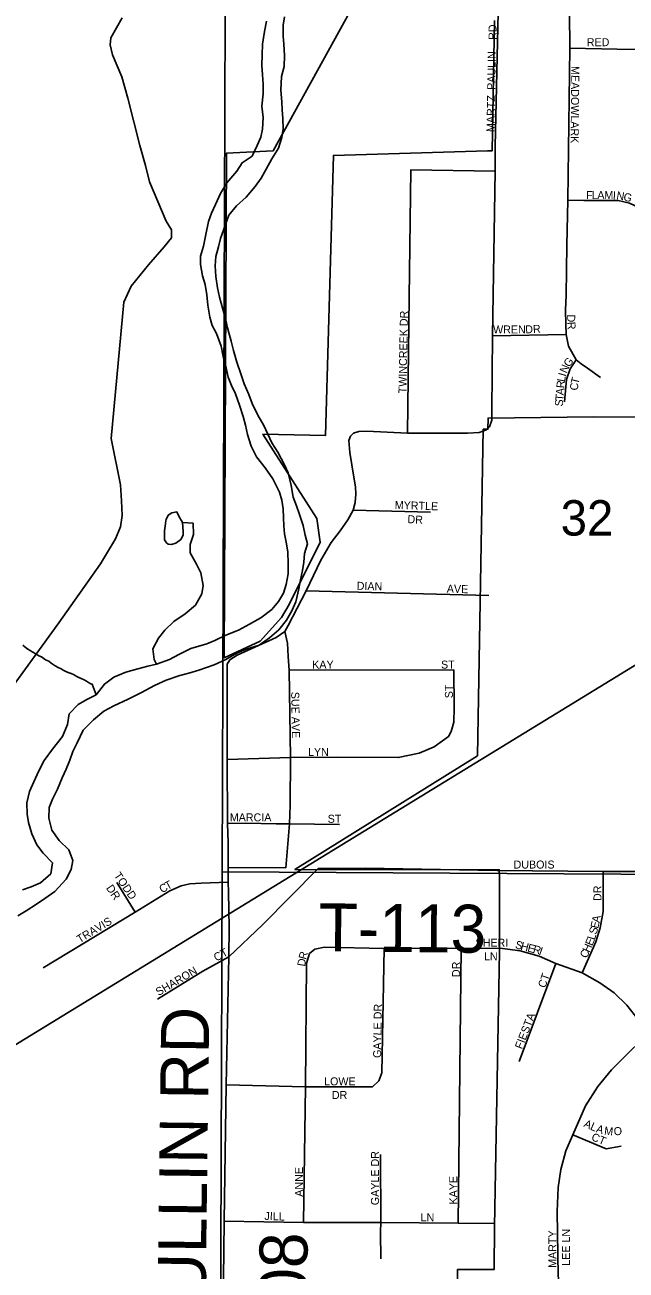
# Model space of a CAD drawing. Extents: x 0 to 1064, y 0 to 440.
# Drawn here: x 123.81 to 135.19, y 382.83 to 406.41 of the extents above; entities that cross this region are included whole.
import ezdxf

# ---------------------------------------------------------------- set-up
doc = ezdxf.new("R2010")
doc.units = 0
for name, color, linetype in [('GM_X_City_Street', 7, 'Continuous'), ('GM_X_City_Street_Text', 7, 'Continuous'), ('GM_X_Corporation', 7, 'Continuous'), ('GM_X_Major_River', 7, 'Continuous'), ('GM_X_Minor_River', 7, 'Continuous'), ('GM_X_Rail_Line', 7, 'Continuous'), ('GM_X_Section', 7, 'Continuous'), ('GM_X_Section_Text', 7, 'Continuous'), ('GM_X_Township_Road', 7, 'Continuous'), ('GM_X_Township_Road_Text', 7, 'Continuous'), ('GM_X_Township_Subdivision', 7, 'Continuous'), ('GM_X_Township_Subdivision_Text', 7, 'Continuous')]:
    doc.layers.add(name, color=color, linetype=linetype)

msp = doc.modelspace()

# ---------------------------------------------------------------- linework, layer by layer
at = {"layer": 'GM_X_City_Street'}
for points in [[(132.714, 404.106), (132.772, 406.652)], [(132.75, 390.394), (134.757, 390.374), (136.62, 390.376), (136.91, 390.371), (137.013, 390.348), (137.089, 390.3), (137.137, 390.226), (137.163, 389.662), (137.204, 389.562), (137.277, 389.485), (137.431, 389.468), (143.546, 390.366), (143.775, 390.453), (143.847, 390.611), (143.862, 390.856), (143.883, 391.754)], [(134.365, 388.457), (134.621, 389.046), (134.706, 389.31), (134.757, 389.618), (134.757, 390.374)], [(136.383, 385.385), (136.383, 385.386), (136.355, 385.759), (136.296, 386.09), (136.182, 386.424), (135.962, 386.853), (135.62, 387.294), (135.415, 387.581), (135.206, 387.843), (134.969, 388.08), (134.694, 388.266), (134.365, 388.457), (133.864, 388.634), (133.548, 388.774), (133.191, 388.871), (132.854, 388.914)], [(133.169, 386.775), (133.864, 388.634)], [(134.077, 381.501), (133.99, 382.156), (133.907, 382.717), (133.889, 383.935), (133.907, 384.388), (133.958, 384.734), (134.056, 385.085), (134.188, 385.386), (134.424, 385.936), (134.656, 386.306), (134.915, 386.621), (135.313, 387.018), (135.62, 387.294), (135.828, 387.408), (136.048, 387.541), (136.273, 387.632), (136.465, 387.671), (137.119, 387.679)], [(134.188, 385.386), (134.817, 385.126), (135.1, 385.173)]]:
    msp.add_lwpolyline(points, dxfattribs=at)
at = {"layer": 'GM_X_Corporation'}
for points in [[(132.702, 406.491), (132.661, 404.025), (132.568, 404.021), (129.652, 403.936), (129.505, 398.633), (128.317, 398.656), (129.339, 397.063), (129.401, 396.612), (128.814, 395.433), (128.666, 395.184), (128.264, 394.736), (127.583, 394.424), (127.627, 403.978), (128.514, 404.024), (129.959, 406.642)], [(136.812, 379.062), (134.041, 375.398), (132.648, 375.469), (132.646, 377.376), (132.402, 377.376), (132.652, 379.725), (132.044, 379.725), (132.002, 382.841), (132.698, 382.84), (132.703, 383.651), (132.794, 388.86), (132.795, 390.281), (132.793, 390.407), (128.924, 390.41), (132.38, 392.567), (132.49, 398.749), (132.578, 398.749), (132.581, 398.961), (134.575, 398.988), (135.551, 398.978)]]:
    msp.add_lwpolyline(points, dxfattribs=at)
at = {"layer": 'GM_X_Major_River'}
for points in [[(126.741, 394.084), (126.912, 394.134), (127.102, 394.19), (127.396, 394.292), (127.617, 394.39), (127.82, 394.513), (127.998, 394.587), (128.243, 394.66), (128.441, 394.801), (128.62, 394.954), (128.765, 395.133), (128.866, 395.313), (128.938, 395.481), (128.999, 395.729), (129.027, 395.898), (129.068, 396.073), (129.091, 396.231), (129.107, 396.395), (129.16, 396.582), (129.116, 396.747), (129.078, 396.93), (129.011, 397.138), (128.954, 397.298), (128.892, 397.464), (128.849, 397.683), (128.795, 397.922), (128.726, 398.076), (128.599, 398.316), (128.488, 398.495), (128.407, 398.655), (128.333, 398.821), (128.223, 399.018), (128.113, 399.24), (128.051, 399.411), (127.965, 399.608), (127.897, 399.798), (127.824, 400.019), (127.757, 400.239), (127.713, 400.417), (127.647, 400.673), (127.609, 400.845), (127.559, 401.022), (127.498, 401.254), (127.46, 401.426), (127.423, 401.645), (127.41, 401.846), (127.427, 402.022), (127.474, 402.203), (127.515, 402.36), (127.58, 402.541), (127.672, 402.806), (127.816, 402.984), (128.002, 403.144), (128.172, 403.346), (128.285, 403.507), (128.38, 403.675), (128.483, 403.873), (128.609, 404.076), (128.675, 404.275), (128.698, 404.438), (128.697, 404.633), (128.683, 404.797), (128.674, 404.949), (128.656, 405.169), (128.669, 405.43), (128.722, 405.623), (128.728, 405.829), (128.715, 406.042), (128.701, 406.194), (128.7, 406.401), (128.728, 406.558)], [(128.387, 406.476), (128.345, 406.282), (128.308, 406.04), (128.303, 405.84), (128.298, 405.645), (128.312, 405.463), (128.319, 405.286), (128.32, 405.104), (128.296, 404.868), (128.321, 404.655), (128.309, 404.436), (128.275, 404.279), (128.21, 404.123), (128.114, 403.925), (127.922, 403.796), (127.821, 403.64), (127.633, 403.414), (127.513, 403.217), (127.416, 403.007), (127.345, 402.844), (127.287, 402.682), (127.238, 402.44), (127.19, 402.216), (127.136, 402.029), (127.132, 401.871), (127.175, 401.658), (127.225, 401.492), (127.257, 401.297), (127.276, 401.102), (127.312, 400.876), (127.357, 400.717), (127.438, 400.563), (127.529, 400.324), (127.566, 400.129), (127.621, 399.914), (127.659, 399.737), (127.721, 399.578), (127.796, 399.418), (127.876, 399.209), (127.943, 398.989), (127.987, 398.83), (128.025, 398.652), (128.092, 398.432), (128.196, 398.229), (128.36, 398.018), (128.507, 397.814), (128.628, 397.561), (128.678, 397.408), (128.698, 397.244), (128.706, 397.073), (128.714, 396.921), (128.728, 396.769), (128.766, 396.579), (128.786, 396.421), (128.793, 396.208), (128.794, 396.014), (128.758, 395.808), (128.705, 395.645), (128.61, 395.489), (128.485, 395.335), (128.28, 395.176), (128.065, 395.059), (127.856, 394.943), (127.617, 394.852), (127.408, 394.748), (127.254, 394.685), (126.949, 394.601), (126.727, 394.485), (126.549, 394.393), (126.304, 394.302), (126.139, 394.263), (125.95, 394.213), (125.724, 394.152), (125.497, 394.055), (125.317, 393.925), (125.16, 393.723), (124.982, 393.63), (124.816, 393.537), (124.647, 393.359), (124.618, 393.159), (124.521, 392.93)], [(123.674, 389.535), (123.834, 389.628), (124.032, 389.757), (124.186, 389.863), (124.378, 389.998), (124.59, 390.229), (124.686, 390.415), (124.715, 390.585), (124.641, 390.787), (124.458, 390.962), (124.323, 391.16), (124.262, 391.387), (124.268, 391.587), (124.332, 391.744), (124.428, 391.936), (124.513, 392.146), (124.59, 392.315), (124.661, 392.483), (124.72, 392.646), (124.797, 392.814), (124.912, 393.054), (125.106, 393.25), (125.304, 393.409), (125.495, 393.514), (125.765, 393.641), (126.017, 393.768), (126.263, 393.895), (126.484, 393.999), (126.741, 394.084)], [(124.521, 392.93), (124.333, 392.692), (124.175, 392.477), (124.073, 392.279), (123.977, 392.075), (123.899, 391.888), (123.845, 391.677), (123.852, 391.464), (123.878, 391.305), (123.939, 391.091), (124.037, 390.882), (124.154, 390.721), (124.331, 390.54), (124.302, 390.334), (124.103, 390.163), (123.931, 390.082), (123.766, 390.031)]]:
    msp.add_lwpolyline(points, dxfattribs=at)
at = {"layer": 'GM_X_Minor_River'}
for points in [[(126.792, 396.982), (126.769, 397.031), (126.74, 397.08), (126.688, 397.185), (126.591, 397.169), (126.523, 397.122), (126.485, 397.044), (126.478, 397.014), (126.469, 396.917), (126.455, 396.826), (126.453, 396.766)], [(126.304, 394.302), (126.258, 394.388), (126.233, 394.595), (126.341, 394.793), (126.46, 394.948), (126.628, 395.108), (126.844, 395.254), (127.043, 395.42), (127.158, 395.636), (127.186, 395.793), (127.144, 396.031), (127.057, 396.197), (126.941, 396.407), (126.939, 396.565), (127.005, 396.758), (126.998, 396.971)], [(126.453, 396.766), (126.456, 396.656), (126.491, 396.601), (126.521, 396.575), (126.587, 396.568), (126.667, 396.596), (126.76, 396.661), (126.804, 396.745), (126.806, 396.817), (126.792, 396.982)], [(126.998, 396.971), (126.792, 396.982)], [(125.16, 393.723), (125.085, 393.926), (125.058, 393.929), (125.016, 393.955), (124.974, 393.98), (124.933, 394.005), (124.878, 394.031), (124.83, 394.05), (124.782, 394.075), (124.74, 394.101), (124.686, 394.126), (124.632, 394.145), (124.584, 394.165), (124.536, 394.19), (124.494, 394.215), (124.44, 394.241), (124.386, 394.272), (124.308, 394.323), (124.261, 394.36), (124.2, 394.386), (124.123, 394.442), (124.075, 394.462), (124.015, 394.5), (123.949, 394.537), (123.907, 394.563), (123.865, 394.588), (123.817, 394.625), (123.77, 394.663)]]:
    msp.add_lwpolyline(points, dxfattribs=at)
at = {"layer": 'GM_X_Rail_Line'}
msp.add_lwpolyline([(111.177, 379.476), (120.304, 385.063), (131.83, 392.117), (142.562, 398.69), (143.768, 399.423)], dxfattribs=at)
at = {"layer": 'GM_X_Section'}
for points in [[(127.601, 406.619), (143.975, 406.617), (143.725, 390.273), (127.547, 390.367)], [(127.547, 390.367), (143.725, 390.273), (143.623, 377.052), (143.373, 376.687), (142.743, 376.669), (142.202, 376.626), (141.832, 376.572), (141.113, 376.399), (140.765, 376.267), (140.465, 376.103), (140.059, 375.814), (139.855, 375.63), (139.525, 375.177), (139.367, 374.859), (139.327, 374.69), (139.333, 374.077), (139.293, 373.89), (127.487, 374.158)]]:
    msp.add_lwpolyline(points, close=True, dxfattribs=at)
at = {"layer": 'GM_X_Township_Road'}
for points in [[(123.374, 393.595), (124.453, 395.085), (125.244, 396.204), (125.523, 396.678), (125.619, 396.901), (125.654, 397.119), (125.636, 397.393), (125.619, 397.698), (125.446, 398.577), (125.682, 401.156), (125.823, 401.463), (126.148, 401.863), (126.448, 402.202), (126.585, 402.375), (126.583, 402.527), (126.483, 402.694), (126.167, 403.437), (126.095, 403.748), (125.989, 404.121), (125.761, 405.02), (125.643, 405.424), (125.47, 405.841), (125.426, 406.031), (125.436, 406.164), (125.651, 406.542)], [(132.714, 404.106), (132.718, 403.641), (132.663, 400.517), (132.654, 399.104), (132.65, 398.924), (132.607, 398.794), (132.55, 398.737), (132.411, 398.692), (132.191, 398.676), (131.055, 398.679), (130.283, 398.714), (130.135, 398.709), (130.034, 398.676), (129.978, 398.619), (129.944, 398.535), (129.961, 398.311), (130.001, 398.078), (130.044, 397.806), (130.069, 397.66), (130.077, 397.52), (130.063, 397.362), (130.029, 397.219), (129.927, 397.033), (129.779, 396.829), (129.609, 396.606), (129.411, 396.271), (129.137, 395.69), (128.797, 395.037), (128.729, 394.919), (128.571, 394.804), (127.827, 394.471), (127.693, 394.381), (127.643, 394.3), (127.641, 392.497), (127.649, 391.284), (127.658, 390.925), (127.656, 390.727), (127.661, 390.451), (127.659, 390.172), (127.664, 389.986)], [(127.661, 390.451), (128.751, 390.446)], [(127.671, 388.759), (128.311, 389.368), (129.361, 390.433)], [(129.361, 390.433), (130.251, 390.437), (132.75, 390.394)], [(127.664, 389.986), (127.68, 389.315), (127.671, 388.759), (127.622, 386.333), (127.583, 383.751), (127.487, 375.568)]]:
    msp.add_lwpolyline(points, dxfattribs=at)
at = {"layer": 'GM_X_Township_Subdivision'}
for points in [[(134.121, 406.643), (134.127, 405.965), (134.089, 403.087), (134.075, 402.239), (134.066, 401.765)], [(134.127, 405.965), (135.025, 405.949), (136.736, 405.933), (137.376, 405.921)], [(131.055, 398.679), (131.088, 401.243), (131.118, 403.662), (132.718, 403.641)], [(134.089, 403.087), (134.396, 403.083), (135.043, 403.08), (135.256, 403.034), (135.438, 402.951), (135.619, 402.804), (136.458, 401.983), (136.678, 401.846)], [(134.066, 401.765), (134.057, 401.285), (134.05, 401.013), (134.054, 400.738)], [(134.054, 400.738), (134.057, 400.545), (134.106, 400.324), (134.246, 400.062), (134.342, 399.989), (134.461, 399.909), (134.707, 399.73)], [(132.663, 400.517), (134.057, 400.545)], [(134.246, 400.062), (134.133, 399.896), (134.063, 399.692), (134.026, 399.269)], [(130.029, 397.219), (131.492, 397.181)], [(129.137, 395.69), (132.594, 395.605)], [(128.751, 390.446), (128.818, 391.276), (128.832, 391.632), (128.837, 392.535), (128.812, 394.187), (128.797, 394.449), (128.785, 394.697), (128.729, 394.919)], [(127.641, 392.497), (128.837, 392.535), (129.732, 392.538), (130.879, 392.533), (131.274, 392.616), (131.558, 392.739), (131.832, 392.93), (131.879, 393.025), (131.93, 393.204), (131.937, 393.483), (131.935, 394.195)], [(128.812, 394.187), (131.935, 394.195)], [(127.649, 391.284), (127.993, 391.29), (128.57, 391.28), (128.818, 391.276), (129.769, 391.263)], [(127.659, 390.172), (127.146, 390.153), (126.935, 390.144), (126.769, 390.106), (126.554, 390.01), (125.896, 389.607), (124.157, 388.549)], [(125.896, 389.607), (125.549, 390.168)], [(129.199, 388.822), (129.303, 388.904), (129.484, 388.942), (130.614, 388.919), (132.074, 388.922), (132.854, 388.914)], [(130.395, 386.3), (130.51, 386.409), (130.571, 386.565), (130.614, 388.919)], [(132.012, 383.718), (132.074, 388.922)], [(126.318, 387.958), (127.179, 388.487), (127.671, 388.759)], [(129.087, 383.727), (129.125, 386.3), (129.14, 388.631), (129.199, 388.822)], [(127.622, 386.333), (129.125, 386.3), (130.395, 386.3)], [(130.545, 383.553), (130.548, 383.725), (130.544, 385.016)], [(127.583, 383.751), (129.087, 383.727), (130.548, 383.725), (132.012, 383.718), (132.708, 383.71)], [(130.552, 383.037), (130.544, 383.54), (130.545, 383.553)]]:
    msp.add_lwpolyline(points, dxfattribs=at)

# ---------------------------------------------------------------- texts
at = {"layer": 'GM_X_City_Street_Text'}
for s, height, rotation, p in [('RD', 0.1515, 90, (132.741, 406.123)), ('PAULIN', 0.1515, 89.0614, (132.715, 405.176)), ('MARTZ', 0.1515, 88.8316, (132.701, 404.377)), ('DUBOIS', 0.1515, 0, (133.063, 390.431)), ('DR', 0.1515, 90, (134.728, 389.816)), ('S', 0.152, 73.8007, (134.632, 389.173)), ('E', 0.152, 77.5061, (134.665, 389.286)), ('A', 0.152, 80.2066, (134.69, 389.398)), ('E', 0.152, 67.69, (134.554, 388.956)), ('L', 0.152, 72.2551, (134.599, 389.067)), ('S', 0.152, 345.3607, (133.083, 388.924)), ('H', 0.152, 345.388, (133.187, 388.897)), ('E', 0.152, 345.4081, (133.316, 388.863)), ('R', 0.152, 345.3689, (133.419, 388.836)), ('I', 0.152, 340.8461, (133.532, 388.807)), ('C', 0.152, 66.3261, (134.45, 388.721)), ('H', 0.152, 66.3306, (134.499, 388.831)), ('CT', 0.1515, 70.5566, (133.663, 388.159)), ('FIESTA', 0.1515, 68.8723, (133.223, 387)), ('A', 0.152, 335.8915, (134.38, 385.547)), ('L', 0.152, 335.8915, (134.501, 385.493)), ('A', 0.152, 341.7973, (134.614, 385.443)), ('CT', 0.1515, 337.6289, (134.523, 385.292)), ('M', 0.152, 353.6091, (134.774, 385.394)), ('O', 0.152, 5.4209, (134.967, 385.376)), ('MARTY', 0.1515, 90, (133.875, 382.869)), ('LEE LN', 0.1515, 90, (134.132, 382.909))]:
    msp.add_text(s, height=height, rotation=rotation, dxfattribs=at).set_placement(p)
at = {"layer": 'GM_X_Section_Text'}
msp.add_text('32', height=0.6697, rotation=0, dxfattribs=at).set_placement((133.956, 396.737))
at = {"layer": 'GM_X_Township_Road_Text'}
for s, height, rotation, p in [('T-113', 0.9091, 359.4423, (129.367, 388.865)), ('MARTZPAULLIN RD', 0.90909, 89.2718, (127.158, 376.458)), ('T-108', 0.9091, 89.4386, (129.134, 380.361))]:
    msp.add_text(s, height=height, rotation=rotation, dxfattribs=at).set_placement(p)
at = {"layer": 'GM_X_Township_Subdivision_Text'}
for s, height, rotation, p in [('RED', 0.1515, 0, (134.45, 406.005)), ('MEADOWLARK', 0.1515, 269.4386, (134.158, 405.629)), ('F', 0.152, 359.5628, (134.436, 403.111)), ('L', 0.152, 359.5628, (134.543, 403.11)), ('A', 0.152, 359.5628, (134.649, 403.11)), ('M', 0.152, 359.5265, (134.783, 403.109)), ('I', 0.152, 359.5808, (134.943, 403.107)), ('N', 0.152, 351.1807, (135.004, 403.107)), ('G', 0.152, 345.5502, (135.132, 403.088)), ('TWINCREEK DR', 0.15152, 88.9094, (131.035, 399.43)), ('D', 0.152, 270.6992, (134.078, 400.922)), ('WREN', 0.1515, 0, (132.676, 400.564)), ('DR', 0.1515, 3.011, (133.288, 400.564)), ('R', 0.152, 274.019, (134.08, 400.78)), ('N', 0.152, 66.5833, (134.068, 399.8)), ('G', 0.152, 52.999, (134.116, 399.914)), ('L', 0.152, 80.2232, (134.034, 399.639)), ('I', 0.152, 74.2467, (134.051, 399.74)), ('T', 0.152, 75.818, (134.29, 399.593)), ('A', 0.152, 85.0821, (134.013, 399.39)), ('R', 0.152, 85.0871, (134.024, 399.523)), ('C', 0.152, 85.2847, (134.281, 399.48)), ('S', 0.152, 85.1048, (133.995, 399.178)), ('T', 0.152, 85.0776, (134.004, 399.284)), ('MYRTLE', 0.1515, 357.9915, (130.811, 397.243)), ('DR', 0.1515, 356.9884, (131.051, 396.974)), ('DIAN', 0.1515, 358.3643, (130.091, 395.711)), ('AVE', 0.1515, 358.0261, (131.797, 395.658)), ('KAY', 0.1515, 0, (129.25, 394.218)), ('ST', 0.1515, 0, (131.69, 394.218)), ('ST', 0.1515, 90, (131.915, 393.656)), ('SUE AVE', 0.1515, 270.9873, (128.852, 393.777)), ('LYN', 0.1515, 0, (129.17, 392.565)), ('MARCIA', 0.1515, 0, (127.69, 391.325)), ('ST', 0.1515, 0, (129.543, 391.298)), ('TODD', 0.1515, 304.5097, (125.487, 390.299)), ('DR', 0.1515, 304.5016, (125.341, 390.06)), ('C', 0.152, 30.5222, (126.408, 389.96)), ('T', 0.152, 28.4229, (126.51, 390.021)), ('TRAVIS', 0.1515, 31.1607, (124.848, 389.014)), ('SHERI', 0.1515, 0, (132.343, 388.951)), ('CT', 0.1515, 29.3668, (127.436, 388.667)), ('R', 0.152, 74.7619, (129.135, 388.697)), ('D', 0.152, 80.8251, (129.115, 388.57)), ('DR', 0.1515, 90, (132.05, 388.376)), ('LN', 0.1515, 0, (132.503, 388.693)), ('SHARON', 0.1515, 30.6181, (126.342, 388.014)), ('GAYLE DR', 0.1515, 89.1821, (130.555, 386.843)), ('LOWE', 0.1515, 0, (129.476, 386.325)), ('DR', 0.1515, 0, (129.623, 386.067)), ('GAYLE DR', 0.1515, 90, (130.515, 384.056)), ('ANNE', 0.1515, 90, (129.075, 384.216)), ('KAYE', 0.1515, 90, (131.997, 384.069)), ('JILL', 0.1515, 357.8801, (128.344, 383.778)), ('LN', 0.1515, 0, (131.303, 383.751))]:
    msp.add_text(s, height=height, rotation=rotation, dxfattribs=at).set_placement(p)

doc.saveas('drawing.dxf')
